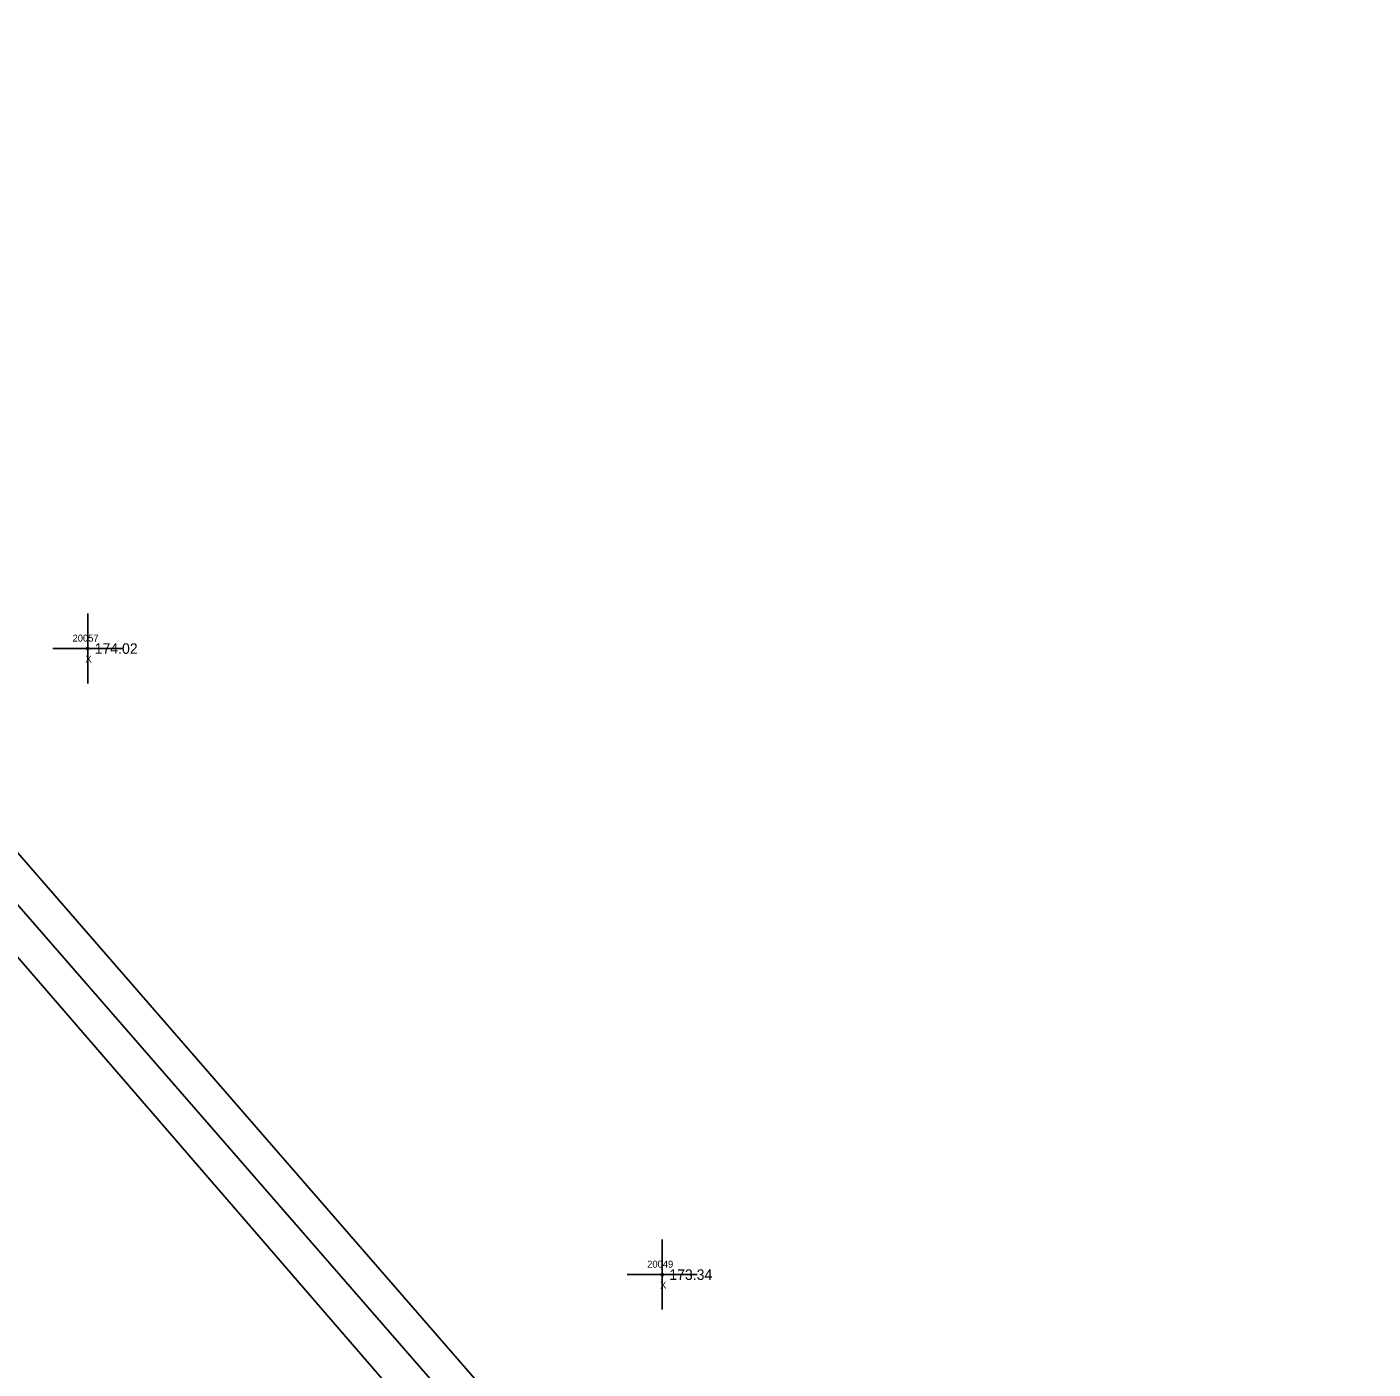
# Model space of a CAD drawing. Extents: x 1970726 to 1971567, y 794829 to 795775.
# Drawn here: x 1970946.1 to 1971138.4, y 795298.6 to 795490.3 of the extents above; entities that cross this region are included whole.
import ezdxf

# ---------------------------------------------------------------- set-up
doc = ezdxf.new("R2010")
doc.units = 0
for name, color, linetype in [('RD_DTM_BkLn1', 7, 'Continuous'), ('RD_EX_Misc', 7, 'Continuous'), ('RD_EX_Misc_txCode', 7, 'Continuous'), ('RD_EX_Road', 7, 'Continuous'), ('RD_EX_TX_Misc_ELEV', 7, 'Continuous'), ('RD_SMD_Locator', 7, 'Continuous')]:
    doc.layers.add(name, color=color, linetype=linetype)

msp = doc.modelspace()

# ---------------------------------------------------------------- linework, layer by layer
at = {"layer": 'RD_DTM_BkLn1'}
msp.add_lwpolyline([(1971548, 794856.6), (1971469.65, 794899.39), (1971398.6, 794938.78), (1971343.49, 794971.52), (1971282.15, 795020.93), (1971214.82, 795076.24), (1971168.26, 795117.15), (1971077.37, 795216.68), (1971014.25, 795285.1), (1970928, 795384.12), (1970874.41, 795450.05), (1970851.19, 795487.2), (1970834.94, 795528.12), (1970822.6, 795571.11), (1970808.56, 795633.3), (1970801.01, 795695.48), (1970787.01, 795762.98)], dxfattribs=at)
at = {"layer": 'RD_EX_Misc'}
for p, q in [((1970954.75, 795396.55), (1970954.75, 795406.55)), ((1970949.75, 795401.55), (1970959.75, 795401.55)), ((1971036.83, 795307.12), (1971036.83, 795317.12)), ((1971031.83, 795312.12), (1971041.83, 795312.12))]:
    msp.add_line(p, q, dxfattribs=at)
at = {"layer": 'RD_EX_Road'}
for points in [[(1971550.5, 794861.13), (1971472.2, 794904.32), (1971401.49, 794943.08), (1971346.58, 794975.73), (1971286.05, 795024.56), (1971217.92, 795079.41), (1971172.76, 795121.06), (1971082.31, 795221.27), (1971017.96, 795288.13), (1970931.75, 795387.33), (1970878.11, 795452.95), (1970856.35, 795489.48), (1970840.29, 795529.45), (1970827.57, 795574.31), (1970814.81, 795635.62), (1970805.04, 795696.13), (1970791.39, 795763.83)], [(1971543.68, 794851.6), (1971507.7, 794872.08), (1971504.76, 794847.96), (1971494.98, 794846.56), (1971488.18, 794883), (1971469.72, 794893.79), (1971395.92, 794934.76), (1971339.47, 794967.38), (1971278.34, 795016.59), (1971212.1, 795072.1), (1971165.04, 795113.96), (1971074.42, 795213.48), (1971010.42, 795281.48), (1970922.49, 795383.19), (1970882.25, 795365.41), (1970854.66, 795404.07), (1970871.45, 795443.76), (1970844.39, 795483.83), (1970828.93, 795526.65), (1970817.76, 795568.61), (1970806.82, 795600.57), (1970787.72, 795602.49), (1970770.58, 795591.56)]]:
    msp.add_lwpolyline(points, dxfattribs=at)
at = {"layer": 'RD_SMD_Locator'}
for centre in [(1970954.75, 795401.55), (1971036.83, 795312.12)]:
    msp.add_circle(centre, 0.15, dxfattribs=at)

# ---------------------------------------------------------------- texts
at = {"layer": 'RD_EX_Misc_txCode'}
for s, p in [('20057', (1970952.59, 795402.55)), ('X', (1970954.43, 795399.55)), ('20049', (1971034.67, 795313.12)), ('X', (1971036.51, 795310.12))]:
    msp.add_text(s, height=1, dxfattribs=at).set_placement(p)
at = {"layer": 'RD_EX_TX_Misc_ELEV'}
for s, p in [('174.02', (1970955.75, 795400.8)), ('173.34', (1971037.83, 795311.37))]:
    msp.add_text(s, height=1.5, dxfattribs=at).set_placement(p)

doc.saveas('drawing.dxf')
